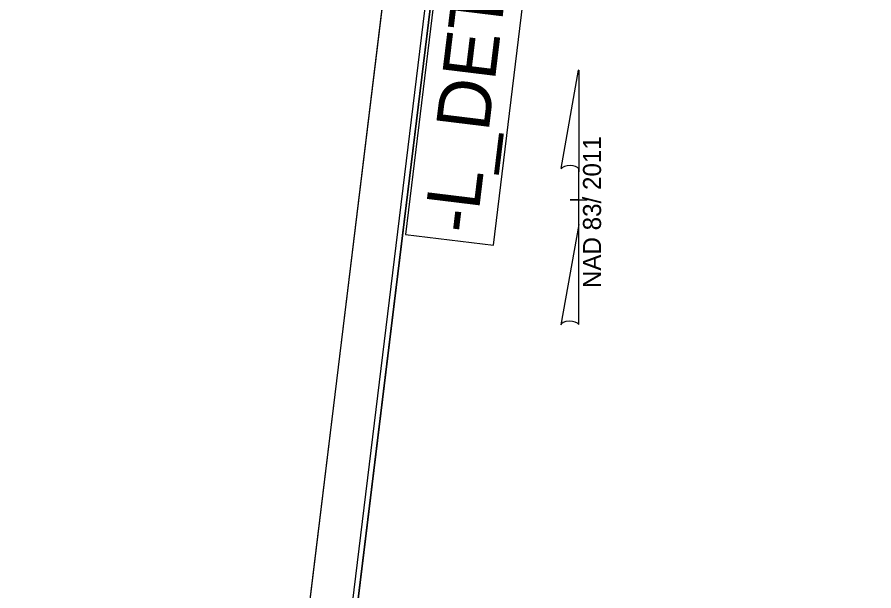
# Model space of a CAD drawing. Extents: x 480344 to 482186, y 489602 to 491961.
# Drawn here: x 480803.3 to 481206.4, y 491421.2 to 491690.9 of the extents above; entities that cross this region are included whole.
import ezdxf

# ---------------------------------------------------------------- set-up
doc = ezdxf.new("R2010")
doc.units = 0
for name, color, linetype in [('Prop DSN Text', 7, 'Continuous'), ('Prop Grid Mask', 7, 'Continuous'), ('Prop North Arrow NAD83 for Plan Sheets CELL', 7, 'Continuous'), ('Sheet Cutting Line CELL', 7, 'Continuous'), ('Sheet Layout Plan Border', 7, 'Continuous'), ('Sheet North Arrow Point CELL', 7, 'Continuous'), ('Sheet Plan CELL', 7, 'Continuous'), ('Sheet Plot Border Inside CELL', 7, 'Continuous'), ('Sheet Plot Border Outside CELL', 7, 'Continuous')]:
    doc.layers.add(name, color=color, linetype=linetype)

msp = doc.modelspace()

# ---------------------------------------------------------------- linework, layer by layer
at = {"layer": 'Prop Grid Mask'}
msp.add_lwpolyline([(481004.73, 491742.29), (480985.97, 491588.74), (481027.37, 491583.68), (481046.13, 491737.24)], close=True, dxfattribs=at)
at = {"layer": 'Prop North Arrow NAD83 for Plan Sheets CELL'}
for p, q in [((481059.27, 491619.69), (481067.47, 491666.04)), ((481067.52, 491666.04), (481067.47, 491666.04)), ((481067.52, 491666.04), (481067.47, 491666.04)), ((481067.52, 491666.04), (481067.52, 491618.24)), ((481067.52, 491593.44), (481067.52, 491619.64)), ((481067.52, 491618.24), (481067.52, 491619.59)), ((481063.52, 491605.04), (481063.47, 491605.04)), ((481067.07, 491605.04), (481063.52, 491605.04)), ((481063.57, 491605.04), (481071.57, 491605.04)), ((481067.52, 491593.44), (481059.17, 491546.19)), ((481067.57, 491546.39), (481067.52, 491593.44))]:
    msp.add_line(p, q, dxfattribs=at)
for centre, start_param, end_param in [((481063.4, 491619.19), 0.216388, 2.908219), ((481063.4, 491546.02), 0.201328, 3.141593)]:
    msp.add_ellipse(centre, major_axis=(4.23, -0.03), ratio=0.461098, start_param=start_param, end_param=end_param, dxfattribs=at)
at = {"layer": 'Sheet Cutting Line CELL'}
msp.add_line((481007.36, 491960.62), (480803.26, 490289.54), dxfattribs=at)
at = {"layer": 'Sheet Layout Plan Border'}
for points in [[(481091.9, 490519.7), (481587.5, 490459.17), (481698.34, 490347.94), (481789.23, 490336.84), (481888.02, 490324.77), (481894.09, 490374.4), (482045.29, 491612.38), (481950.42, 491623.25), (481975.38, 491825.26), (481441.95, 491890.42), (481190.71, 491844.78), (481175.64, 491721.42), (481003.37, 491742.46), (480851.83, 490501.7)], [(481091.9, 490519.7), (481587.5, 490459.17), (481698.34, 490347.94), (481789.23, 490336.84), (481888.02, 490324.77), (481894.09, 490374.4), (482045.29, 491612.38), (481950.42, 491623.25), (481955.43, 491661.97), (481633.66, 491701.27), (481441.95, 491890.42), (481190.71, 491844.78), (481175.64, 491721.42), (481003.37, 491742.46), (480851.83, 490501.7)]]:
    msp.add_lwpolyline(points, close=True, dxfattribs=at)
at = {"layer": 'Sheet North Arrow Point CELL'}
msp.add_line((481067.52, 491666.04), (481067.52, 491666.04), dxfattribs=at)
at = {"layer": 'Sheet Plan CELL'}
for points in [[(481027.63, 491941.04), (480845.77, 490452.07), (481888.02, 490324.77), (482069.88, 491813.72)], [(481888.02, 490324.77), (480845.79, 490452.04), (481003.36, 491742.45), (481152.32, 491724.27), (481176.58, 491922.83), (482069.88, 491813.72)]]:
    msp.add_lwpolyline(points, close=True, dxfattribs=at)
at = {"layer": 'Sheet Plot Border Inside CELL'}
msp.add_lwpolyline([(481871.91, 490172.11), (482073.88, 491825.81), (481026.67, 491953.73), (480824.69, 490300.02)], close=True, dxfattribs=at)
at = {"layer": 'Sheet Plot Border Outside CELL'}
msp.add_lwpolyline([(481890.19, 490156.78), (482094.29, 491827.87), (481007.36, 491960.62), (480803.26, 490289.54)], close=True, dxfattribs=at)

# ---------------------------------------------------------------- texts
at = {"layer": 'Prop DSN Text'}
msp.add_text('-L_DET1-', height=25, rotation=83.0365, dxfattribs=at).set_placement((481019.24, 491588.65))
at = {"layer": 'Prop North Arrow NAD83 for Plan Sheets CELL'}
msp.add_text('NAD 83/ 2011', height=8.5, rotation=90, dxfattribs=at).set_placement((481078.04, 491563.52))

doc.saveas('drawing.dxf')
